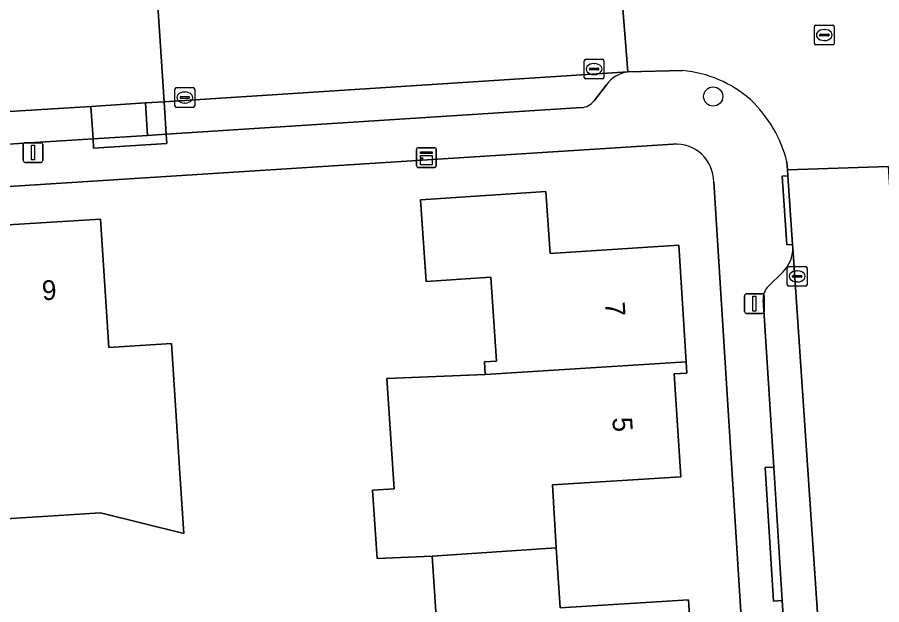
# Model space of a CAD drawing. Extents: x 159626 to 160723, y 388173 to 389416.
# Drawn here: x 160218.48 to 160262.39, y 388380.87 to 388410.69 of the extents above; entities that cross this region are included whole.
import ezdxf

# ---------------------------------------------------------------- set-up
doc = ezdxf.new("R2010")
doc.units = 0
for name, color, linetype in [('IMGEO_Boom', 7, 'Continuous'), ('IMGEO_Erf', 7, 'Continuous'), ('IMGEO_Kast', 7, 'Continuous'), ('IMGEO_Kolk', 7, 'Continuous'), ('IMGEO_Lichtmast', 7, 'Continuous'), ('IMGEO_Pand', 7, 'Continuous'), ('IMGEO_Pand_nummerreeks', 7, 'Continuous'), ('IMGEO_Parkeervlak_open', 7, 'Continuous'), ('IMGEO_Rijbaan_lokaal_open', 7, 'Continuous'), ('IMGEO_Rioolput', 7, 'Continuous'), ('IMGEO_Voetpad_open', 7, 'Continuous')]:
    doc.layers.add(name, color=color, linetype=linetype)

msp = doc.modelspace()

# ---------------------------------------------------------------- linework, layer by layer
at = {"layer": 'IMGEO_Boom'}
msp.add_circle((160253.835, 388406.67), 0.489, dxfattribs=at)
at = {"layer": 'IMGEO_Erf'}
for points in [[(160251.805, 388404.253), (160151.369, 388397.86), (160149.951, 388401.077), (160148.565, 388400.687), (160087.156, 388383.386)], [(160257.711, 388341.192), (160253.862, 388402.327)], [(160239.829, 388379.258), (160239.559, 388383.34), (160236.768, 388383.21), (160236.531, 388386.684), (160237.629, 388386.757), (160237.259, 388392.345), (160242.255, 388392.552), (160242.213, 388393.194), (160242.821, 388393.234), (160242.539, 388397.494), (160239.246, 388397.276), (160238.971, 388401.426), (160245.324, 388401.846), (160245.549, 388398.707), (160252.087, 388399.126), (160252.465, 388393.197), (160252.501, 388392.628), (160251.854, 388392.587), (160252.186, 388387.358), (160245.662, 388386.946), (160245.864, 388383.755), (160246.058, 388380.701), (160252.582, 388381.114), (160252.913, 388375.886)], [(160216.897, 388400.086), (160222.704, 388400.451), (160223.125, 388393.921), (160226.315, 388394.126), (160226.636, 388389.137), (160226.723, 388387.785), (160226.935, 388384.485), (160222.713, 388385.539), (160217.896, 388385.229)]]:
    msp.add_lwpolyline(points, dxfattribs=at)
msp.add_arc((160251.935, 388402.33), 1.927, 359.9045, 93.8631, dxfattribs=at)
at = {"layer": 'IMGEO_Kast'}
for p, q in [((160238.839, 388404.068), (160239.68, 388404.068)), ((160239.68, 388404.068), (160238.839, 388404.068)), ((160238.764, 388403.143), (160238.764, 388403.984)), ((160238.764, 388403.984), (160238.764, 388403.143)), ((160239.764, 388403.993), (160239.764, 388403.152)), ((160239.764, 388403.152), (160239.764, 388403.993)), ((160239.689, 388403.068), (160238.848, 388403.068)), ((160238.848, 388403.068), (160239.689, 388403.068))]:
    msp.add_line(p, q, dxfattribs=at)
for points in [[(160238.959, 388403.858), (160239.559, 388403.858), (160239.559, 388403.773), (160238.959, 388403.773), (160238.959, 388403.858)], [(160238.959, 388403.683), (160239.559, 388403.683), (160239.559, 388403.194), (160238.959, 388403.194), (160238.959, 388403.683)]]:
    msp.add_lwpolyline(points, dxfattribs=at)
msp.add_circle((160239.043, 388403.532), 0.0377, dxfattribs=at)
for centre, start, end in [((160238.842, 388403.99), 92.4484, 184.2845), ((160238.842, 388403.99), 92.4484, 184.2845), ((160239.686, 388403.99), 2.4484, 94.2845), ((160239.686, 388403.99), 2.4484, 94.2845), ((160238.842, 388403.146), 182.4484, 274.2845), ((160238.842, 388403.146), 182.4484, 274.2845), ((160239.686, 388403.146), 272.4484, 4.2845), ((160239.686, 388403.146), 272.4484, 4.2845)]:
    msp.add_arc(centre, 0.0779, start, end, dxfattribs=at)
at = {"layer": 'IMGEO_Kolk'}
for p, q in [((160247.285, 388407.637), (160247.285, 388408.489)), ((160247.36, 388408.563), (160248.212, 388408.563)), ((160248.286, 388408.489), (160248.286, 388407.637)), ((160247.544, 388408.057), (160247.544, 388408.069)), ((160247.982, 388408.02), (160247.584, 388408.02)), ((160247.587, 388408.106), (160247.985, 388408.106)), ((160247.773, 388408.343), (160247.798, 388408.343)), ((160248.028, 388408.069), (160248.028, 388408.057)), ((160248.212, 388407.563), (160247.36, 388407.563)), ((160247.796, 388407.783), (160247.771, 388407.783)), ((160226.566, 388407.12), (160227.418, 388407.12)), ((160226.491, 388406.194), (160226.491, 388407.046)), ((160226.793, 388406.663), (160227.191, 388406.663)), ((160226.979, 388406.9), (160227.004, 388406.9)), ((160227.492, 388407.046), (160227.492, 388406.194)), ((160226.75, 388406.614), (160226.75, 388406.626)), ((160227.188, 388406.577), (160226.79, 388406.577)), ((160227.002, 388406.34), (160226.977, 388406.34)), ((160227.234, 388406.626), (160227.234, 388406.614)), ((160227.418, 388406.12), (160226.566, 388406.12)), ((160257.599, 388397.113), (160257.599, 388397.965)), ((160257.674, 388398.039), (160258.526, 388398.039)), ((160258.6, 388397.965), (160258.6, 388397.113)), ((160257.858, 388397.533), (160257.858, 388397.545)), ((160258.296, 388397.496), (160257.898, 388397.496)), ((160257.901, 388397.582), (160258.299, 388397.582)), ((160258.087, 388397.819), (160258.112, 388397.819)), ((160258.342, 388397.545), (160258.342, 388397.533)), ((160258.526, 388397.039), (160257.674, 388397.039)), ((160258.11, 388397.259), (160258.085, 388397.259))]:
    msp.add_line(p, q, dxfattribs=at)
for points in [[(160247.285, 388407.637), (160247.285, 388408.489)], [(160247.36, 388408.563), (160248.212, 388408.563)], [(160248.286, 388408.489), (160248.286, 388407.637)], [(160248.212, 388407.563), (160247.36, 388407.563)], [(160226.566, 388407.12), (160227.418, 388407.12)], [(160226.491, 388406.194), (160226.491, 388407.046)], [(160227.492, 388407.046), (160227.492, 388406.194)], [(160227.418, 388406.12), (160226.566, 388406.12)], [(160257.599, 388397.113), (160257.599, 388397.965)], [(160257.674, 388398.039), (160258.526, 388398.039)], [(160258.6, 388397.965), (160258.6, 388397.113)], [(160258.526, 388397.039), (160257.674, 388397.039)]]:
    msp.add_lwpolyline(points, dxfattribs=at)
for centre, radius, start, end in [((160247.362, 388408.487), 0.0765, 91.552, 178.448), ((160247.362, 388408.487), 0.0765, 91.552, 178.448), ((160248.21, 388408.487), 0.0765, 1.552, 88.448), ((160248.21, 388408.487), 0.0765, 1.552, 88.448), ((160247.584, 388408.066), 0.0403, 85.8775, 175.7526), ((160247.581, 388408.056), 0.0366, 178.938, 274.7102), ((160247.985, 388408.063), 0.043, 264.8664, 352.4533), ((160247.989, 388408.068), 0.0386, 1.7309, 96.639), ((160247.362, 388407.639), 0.0765, 181.552, 268.448), ((160247.362, 388407.639), 0.0765, 181.552, 268.448), ((160248.21, 388407.639), 0.0765, 271.552, 358.448), ((160248.21, 388407.639), 0.0765, 271.552, 358.448), ((160226.568, 388407.044), 0.0765, 91.552, 178.448), ((160226.568, 388407.044), 0.0765, 91.552, 178.448), ((160227.416, 388407.044), 0.0765, 1.552, 88.448), ((160227.416, 388407.044), 0.0765, 1.552, 88.448), ((160226.79, 388406.623), 0.0403, 85.8775, 175.7526), ((160227.195, 388406.625), 0.0386, 1.7309, 96.639), ((160226.568, 388406.196), 0.0765, 181.552, 268.448), ((160226.568, 388406.196), 0.0765, 181.552, 268.448), ((160226.787, 388406.613), 0.0366, 178.938, 274.7102), ((160227.191, 388406.62), 0.043, 264.8664, 352.4533), ((160227.416, 388406.196), 0.0765, 271.552, 358.448), ((160227.416, 388406.196), 0.0765, 271.552, 358.448), ((160257.676, 388397.963), 0.0765, 91.552, 178.448), ((160257.676, 388397.963), 0.0765, 91.552, 178.448), ((160258.524, 388397.963), 0.0765, 1.552, 88.448), ((160258.524, 388397.963), 0.0765, 1.552, 88.448), ((160257.898, 388397.542), 0.0403, 85.8775, 175.7526), ((160257.895, 388397.532), 0.0366, 178.938, 274.7102), ((160258.299, 388397.539), 0.043, 264.8664, 352.4533), ((160258.303, 388397.544), 0.0386, 1.7309, 96.639), ((160257.676, 388397.115), 0.0765, 181.552, 268.448), ((160257.676, 388397.115), 0.0765, 181.552, 268.448), ((160258.524, 388397.115), 0.0765, 271.552, 358.448), ((160258.524, 388397.115), 0.0765, 271.552, 358.448)]:
    msp.add_arc(centre, radius, start, end, dxfattribs=at)
for centre, major_axis, ratio, start_param, end_param in [((160247.772, 388408.063), (-0.387, 0.002), 0.722429, 4.712389, 7.853982), ((160247.797, 388408.063), (-0.39, 0.002), 0.717154, 1.570796, 4.712389), ((160226.978, 388406.62), (-0.387, 0.002), 0.722429, 4.712389, 7.853982), ((160227.003, 388406.62), (-0.39, 0.002), 0.717154, 1.570796, 4.712389), ((160258.086, 388397.539), (-0.387, 0.002), 0.722429, 4.712389, 7.853982), ((160258.111, 388397.539), (-0.39, 0.002), 0.717154, 1.570796, 4.712389)]:
    msp.add_ellipse(centre, major_axis=major_axis, ratio=ratio, start_param=start_param, end_param=end_param, dxfattribs=at)
at = {"layer": 'IMGEO_Lichtmast'}
for p, q in [((160218.786, 388403.427), (160218.786, 388404.227)), ((160218.786, 388404.227), (160218.786, 388403.427)), ((160218.886, 388404.327), (160219.676, 388404.327)), ((160219.676, 388404.327), (160218.886, 388404.327)), ((160219.776, 388404.227), (160219.776, 388403.427)), ((160219.776, 388403.427), (160219.776, 388404.227)), ((160219.676, 388403.327), (160218.886, 388403.327)), ((160218.886, 388403.327), (160219.676, 388403.327)), ((160255.427, 388395.754), (160255.427, 388396.554)), ((160255.427, 388396.554), (160255.427, 388395.754)), ((160255.527, 388396.654), (160256.317, 388396.654)), ((160256.317, 388396.654), (160255.527, 388396.654)), ((160256.417, 388396.554), (160256.417, 388395.754)), ((160256.417, 388395.754), (160256.417, 388396.554)), ((160256.317, 388395.654), (160255.527, 388395.654)), ((160255.527, 388395.654), (160256.317, 388395.654))]:
    msp.add_line(p, q, dxfattribs=at)
for points in [[(160219.206, 388404.202), (160219.356, 388404.202), (160219.356, 388403.452), (160219.206, 388403.452), (160219.206, 388404.202)], [(160255.847, 388396.529), (160255.997, 388396.529), (160255.997, 388395.779), (160255.847, 388395.779), (160255.847, 388396.529)]]:
    msp.add_lwpolyline(points, dxfattribs=at)
for centre, start, end in [((160218.886, 388404.227), 90, 180), ((160218.886, 388404.227), 90, 180), ((160219.676, 388404.227), 0, 90), ((160219.676, 388404.227), 360, 90), ((160218.886, 388403.427), 180, 270), ((160218.886, 388403.427), 180, 270), ((160219.676, 388403.427), 270, 0), ((160219.676, 388403.427), 270, 0), ((160255.527, 388396.554), 90, 180), ((160255.527, 388396.554), 90, 180), ((160256.317, 388396.554), 0, 90), ((160256.317, 388396.554), 360, 90), ((160255.527, 388395.754), 180, 270), ((160255.527, 388395.754), 180, 270), ((160256.317, 388395.754), 270, 0), ((160256.317, 388395.754), 270, 0)]:
    msp.add_arc(centre, 0.1, start, end, dxfattribs=at)
at = {"layer": 'IMGEO_Pand'}
for points in [[(160242.255, 388392.552), (160252.465, 388393.197), (160252.087, 388399.126), (160245.549, 388398.707), (160245.324, 388401.846), (160238.971, 388401.426), (160239.246, 388397.276), (160242.539, 388397.494), (160242.821, 388393.234), (160242.213, 388393.194)], [(160216.897, 388400.086), (160217.595, 388389.904), (160217.896, 388385.229), (160222.713, 388385.539), (160226.935, 388384.485), (160226.723, 388387.785), (160226.636, 388389.137), (160226.315, 388394.126), (160223.125, 388393.921), (160222.704, 388400.451)], [(160245.864, 388383.755), (160245.662, 388386.946), (160252.186, 388387.358), (160251.854, 388392.587), (160252.501, 388392.628), (160252.465, 388393.197), (160242.255, 388392.552), (160237.259, 388392.345), (160237.629, 388386.757), (160236.531, 388386.684), (160236.768, 388383.21), (160239.559, 388383.34)], [(160245.864, 388383.755), (160239.559, 388383.34), (160239.829, 388379.258), (160243.122, 388379.476), (160243.443, 388374.624), (160253.622, 388375.237), (160253.581, 388375.928), (160252.913, 388375.886), (160252.582, 388381.114), (160246.058, 388380.701)]]:
    msp.add_lwpolyline(points, close=True, dxfattribs=at)
at = {"layer": 'IMGEO_Parkeervlak_open'}
for points in [[(160249.493, 388407.916), (160225.938, 388406.401), (160226.044, 388404.758), (160247.138, 388406.107)], [(160247.786, 388406.453), (160248.411, 388407.269)], [(160256.371, 388396.349), (160256.912, 388387.859), (160257.343, 388381.078), (160258.045, 388370.061), (160259.821, 388370.173), (160257.882, 388398.984)], [(160257.379, 388397.76), (160256.639, 388397.043)]]:
    msp.add_lwpolyline(points, dxfattribs=at)
for points in [[(160224.993, 388406.342), (160222.225, 388406.171), (160222.33, 388404.521), (160225.098, 388404.698)], [(160225.938, 388406.401), (160224.993, 388406.342), (160225.098, 388404.698), (160226.044, 388404.758)], [(160222.225, 388406.171), (160211.432, 388405.502), (160211.545, 388403.842), (160222.33, 388404.521)]]:
    msp.add_lwpolyline(points, close=True, dxfattribs=at)
for centre, radius, start, end in [((160249.705, 388406.334), 1.596, 97.6154, 144.1406), ((160247.082, 388406.992), 0.887, 273.6298, 322.5703), ((160256.199, 388398.96), 1.683, 314.5094, 0.8104), ((160257.26, 388396.404), 0.891, 134.2143, 183.5559)]:
    msp.add_arc(centre, radius, start, end, dxfattribs=at)
at = {"layer": 'IMGEO_Rijbaan_lokaal_open'}
for points in [[(160268.903, 388409.261), (160269.168, 388409.243), (160269.34, 388409.231), (160268.981, 388414.341), (160268.676, 388414.321), (160262.869, 388413.948), (160259.126, 388413.707), (160252.536, 388413.289), (160249.091, 388413.07), (160249.493, 388407.916), (160252.291, 388407.988)], [(160212.674, 388410.753), (160211.093, 388410.635), (160211.432, 388405.502), (160222.225, 388406.171), (160224.993, 388406.342), (160225.938, 388406.401), (160225.611, 388411.527)], [(160257.577, 388403.35), (160257.606, 388402.94), (160262.743, 388403.122)]]:
    msp.add_lwpolyline(points, dxfattribs=at)
for points in [[(160249.091, 388413.07), (160243.137, 388412.692), (160239.377, 388412.453), (160231.088, 388411.927), (160226.247, 388411.591), (160225.611, 388411.527), (160225.938, 388406.401), (160249.493, 388407.916)], [(160263.888, 388384.375), (160263.472, 388391.159), (160262.939, 388399.866), (160262.754, 388402.884), (160262.743, 388403.122), (160257.606, 388402.94), (160257.626, 388402.645), (160257.87, 388399.162), (160257.882, 388398.984), (160259.821, 388370.173), (160260.059, 388366.386), (160260.22, 388363.817), (160261.446, 388344.248), (160261.476, 388343.786), (160266.356, 388344.094), (160265.123, 388364.216), (160264.836, 388368.907), (160264.604, 388372.685)]]:
    msp.add_lwpolyline(points, close=True, dxfattribs=at)
for centre, radius, start, end in [((160251.737, 388401.964), 6.049, 48.7761, 84.7502), ((160251.311, 388401.805), 6.453, 13.8504, 46.8604)]:
    msp.add_arc(centre, radius, start, end, dxfattribs=at)
at = {"layer": 'IMGEO_Rioolput'}
for p, q in [((160258.977, 388409.367), (160258.977, 388410.219)), ((160259.052, 388410.293), (160259.904, 388410.293)), ((160259.978, 388410.219), (160259.978, 388409.367)), ((160259.236, 388409.787), (160259.236, 388409.799)), ((160259.674, 388409.75), (160259.276, 388409.75)), ((160259.279, 388409.836), (160259.677, 388409.836)), ((160259.465, 388410.073), (160259.49, 388410.073)), ((160259.72, 388409.799), (160259.72, 388409.787)), ((160259.904, 388409.293), (160259.052, 388409.293)), ((160259.488, 388409.513), (160259.463, 388409.513))]:
    msp.add_line(p, q, dxfattribs=at)
for points in [[(160258.977, 388409.367), (160258.977, 388410.219)], [(160259.052, 388410.293), (160259.904, 388410.293)], [(160259.978, 388410.219), (160259.978, 388409.367)], [(160259.904, 388409.293), (160259.052, 388409.293)]]:
    msp.add_lwpolyline(points, dxfattribs=at)
for centre, radius, start, end in [((160259.054, 388410.217), 0.0765, 91.552, 178.448), ((160259.054, 388410.217), 0.0765, 91.552, 178.448), ((160259.902, 388410.217), 0.0765, 1.552, 88.448), ((160259.902, 388410.217), 0.0765, 1.552, 88.448), ((160259.276, 388409.796), 0.0403, 85.8775, 175.7526), ((160259.273, 388409.786), 0.0366, 178.938, 274.7102), ((160259.677, 388409.793), 0.043, 264.8664, 352.4533), ((160259.681, 388409.798), 0.0386, 1.7309, 96.639), ((160259.054, 388409.369), 0.0765, 181.552, 268.448), ((160259.054, 388409.369), 0.0765, 181.552, 268.448), ((160259.902, 388409.369), 0.0765, 271.552, 358.448), ((160259.902, 388409.369), 0.0765, 271.552, 358.448)]:
    msp.add_arc(centre, radius, start, end, dxfattribs=at)
for centre, major_axis, ratio, start_param, end_param in [((160259.464, 388409.793), (-0.387, 0.002), 0.722429, 4.712389, 7.853982), ((160259.489, 388409.793), (-0.39, 0.002), 0.717154, 1.570796, 4.712389)]:
    msp.add_ellipse(centre, major_axis=major_axis, ratio=ratio, start_param=start_param, end_param=end_param, dxfattribs=at)
at = {"layer": 'IMGEO_Voetpad_open'}
for points in [[(160150.063, 388408.955), (160146.522, 388407.997), (160147.918, 388403.002), (160149.951, 388401.077), (160151.369, 388397.86), (160251.805, 388404.253)], [(160252.291, 388407.988), (160249.493, 388407.916)], [(160248.411, 388407.269), (160247.786, 388406.453)], [(160247.138, 388406.107), (160226.044, 388404.758), (160226.076, 388404.279), (160222.36, 388404.041), (160222.33, 388404.521), (160211.545, 388403.842), (160211.579, 388403.343), (160204.844, 388402.886), (160204.809, 388403.406), (160204.507, 388403.386), (160193.051, 388402.649), (160193.078, 388402.245), (160186.275, 388401.791), (160186.25, 388402.214), (160175.251, 388401.511), (160175.261, 388401.065), (160168.428, 388400.631), (160168.401, 388401.073), (160163.429, 388400.755)], [(160257.882, 388398.984), (160257.87, 388399.162), (160257.567, 388399.142), (160257.345, 388402.629), (160257.626, 388402.645), (160257.606, 388402.94), (160257.577, 388403.35)], [(160253.862, 388402.327), (160257.711, 388341.192)], [(160256.639, 388397.043), (160257.379, 388397.76)], [(160258.286, 388366.275), (160257.839, 388366.24), (160257.598, 388370.029), (160258.045, 388370.061), (160257.343, 388381.078), (160256.893, 388381.052), (160256.476, 388387.842), (160256.912, 388387.859), (160256.371, 388396.349)]]:
    msp.add_lwpolyline(points, dxfattribs=at)
for points in [[(160226.044, 388404.758), (160225.098, 388404.698), (160222.33, 388404.521), (160222.36, 388404.041), (160226.076, 388404.279)], [(160257.626, 388402.645), (160257.345, 388402.629), (160257.567, 388399.142), (160257.87, 388399.162)], [(160256.912, 388387.859), (160256.476, 388387.842), (160256.893, 388381.052), (160257.343, 388381.078)]]:
    msp.add_lwpolyline(points, close=True, dxfattribs=at)
for centre, radius, start, end in [((160251.737, 388401.964), 6.049, 48.7761, 84.7502), ((160249.705, 388406.334), 1.596, 97.6154, 144.1406), ((160247.082, 388406.992), 0.887, 273.6298, 322.5703), ((160251.311, 388401.805), 6.453, 13.8504, 46.8604), ((160251.935, 388402.33), 1.927, 359.9045, 93.8631), ((160256.199, 388398.96), 1.683, 314.5094, 0.8104), ((160257.26, 388396.404), 0.891, 134.2143, 183.5559)]:
    msp.add_arc(centre, radius, start, end, dxfattribs=at)

# ---------------------------------------------------------------- texts
at = {"layer": 'IMGEO_Pand_nummerreeks'}
for s, rotation, p in [('9', 3.5392, (160219.76, 388396.32)), ('7', 273.6329, (160248.336, 388396.219)), ('5', 273.6329, (160248.709, 388390.356))]:
    msp.add_text(s, height=1, rotation=rotation, dxfattribs=at).set_placement(p)

doc.saveas('drawing.dxf')
